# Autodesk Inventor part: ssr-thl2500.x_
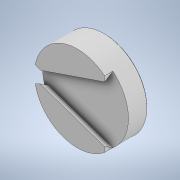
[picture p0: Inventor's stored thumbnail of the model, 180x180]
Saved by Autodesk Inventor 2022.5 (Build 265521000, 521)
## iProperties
Created: 2022-03
Part Number: ssr-thl2500.x_
Material: 一般
Document SubType Name: Modeling
Designer: ImaoCorp
Density: 1 g/cm^3
Appearance: 既定
Sending System: SOLIDWORKS 2020-2020296
MC: AMD64
MC_MODEL: Intel64 Family 6 Model 60 Stepping 3, GenuineIntel
OS: Windows_NT
FRU: Parasolid Version 31.1, build 290,  3- 9-2020
FORMAT: text
GUISE: transmit
KEY: ssr-thl2500
FILE: ssr-thl2500.x_t
DATE: Wed Mar  9 14:26:54 2022
Author: ImaoCorp
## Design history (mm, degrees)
feature "Base1"
node "ソリッド1"
